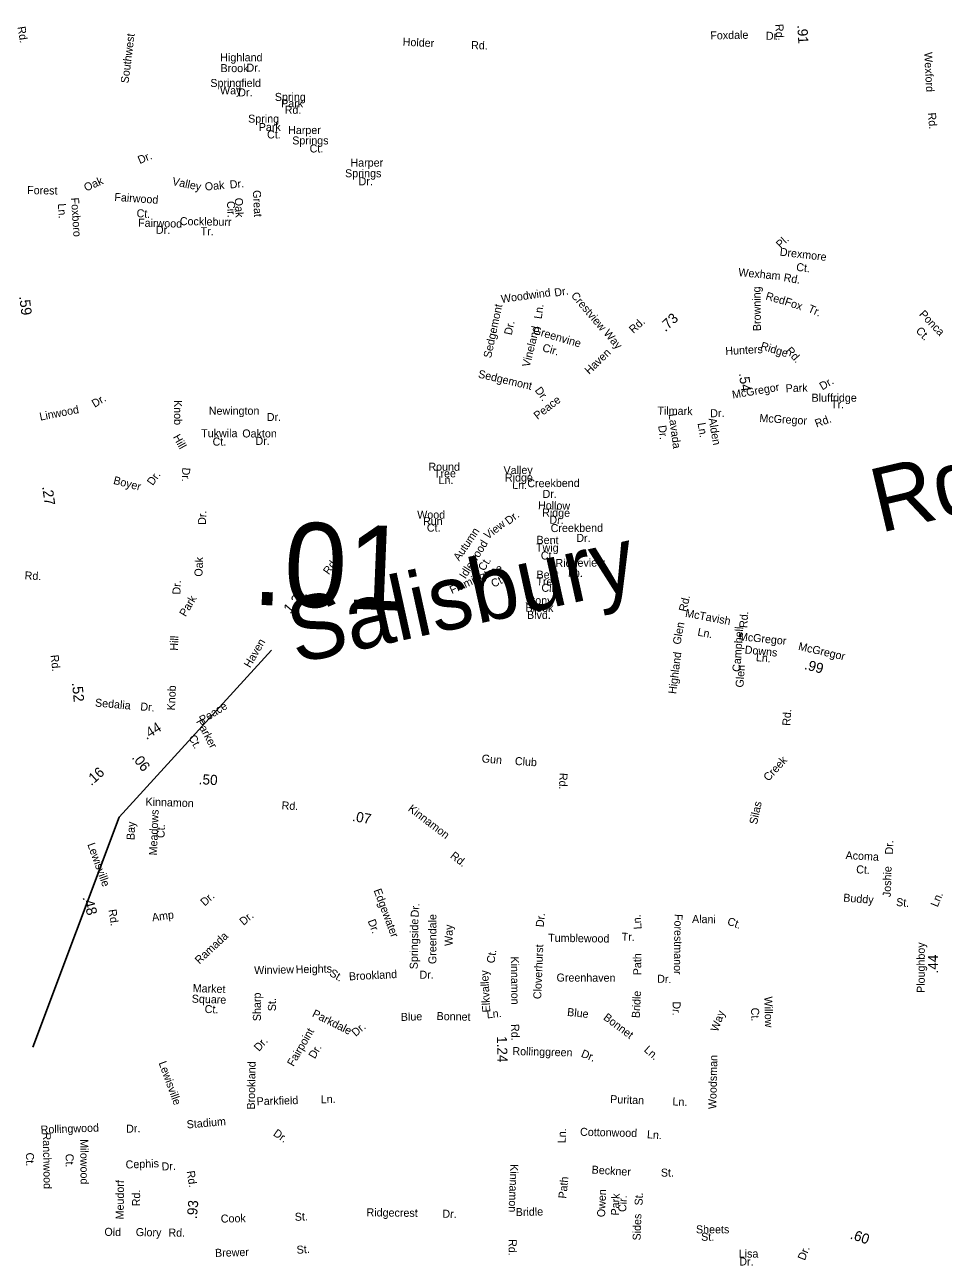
# Model space of a CAD drawing. Extents: x 1553981 to 1780076, y 812965 to 996873.
# Drawn here: x 1628136 to 1629499, y 845055 to 846888 of the extents above; entities that cross this region are included whole.
import ezdxf

# ---------------------------------------------------------------- set-up
doc = ezdxf.new("R2010")
doc.units = 0
for name, color, linetype in [('Exist Road Non-System Type 51 Label', 7, 'Continuous'), ('Exist Road Primary NC Service Mileage Hundredths English Label', 7, 'Continuous'), ('Exist Road Secondary Mileage Hundredths English Label', 7, 'Continuous'), ('Map Preparation Border Antique Large Shape', 7, 'Continuous')]:
    doc.layers.add(name, color=color, linetype=linetype)

msp = doc.modelspace()

# ---------------------------------------------------------------- linework, layer by layer
at = {"layer": 'Exist Road Primary NC Service Mileage Hundredths English Label'}
msp.add_lwpolyline([(1628148.4, 845370.8), (1628276.4, 845712.3), (1628502.7, 845959.8)], dxfattribs=at)

# ---------------------------------------------------------------- texts
at = {"layer": 'Exist Road Non-System Type 51 Label'}
for s, height, rotation, p in [('Southwest', 11.88, 82.8093, (1628290.4, 846800.4)), ('Foxdale', 11.88, 1.1551, (1629153.9, 846865.9)), ('Dr.', 11.88, 0.1484, (1629236.3, 846865.4)), ('Wexford', 11.88, 272.8828, (1629471.1, 846846.8)), ('Rd.', 11.88, 274.1819, (1629476.7, 846757.1)), ('Dr.', 11.88, 22.5389, (1628307.1, 846681)), ('Oak', 11.88, 24.0138, (1628227.5, 846640.2)), ('Valley', 11.88, 348.2903, (1628354.6, 846650.2)), ('Oak', 11.88, 5.1478, (1628404.2, 846641.7)), ('Dr.', 11.88, 5.1478, (1628441.1, 846644.8)), ('Forest', 11.87, 359.1622, (1628140, 846636.5)), ('Fairwood', 11.87, 356.1521, (1628269.2, 846626.5)), ('Great', 11.88, 272.9588, (1628474.9, 846642.1)), ('Ln.', 11.88, 273.727, (1628185.6, 846622.3)), ('Foxboro', 11.88, 273.727, (1628205.1, 846631)), ('Ct.', 11.87, 356.1521, (1628302.1, 846602.5)), ('Cir.', 11.88, 272.9588, (1628436.4, 846626)), ('Oak', 11.88, 272.9588, (1628448.1, 846630.8)), ('Fairwood', 11.88, 358.6849, (1628304.6, 846588.2)), ('Cockleburr', 11.88, 359.1641, (1628366.5, 846590.5)), ('Dr.', 11.88, 359.8348, (1628331.1, 846577.6)), ('Tr.', 11.88, 359.8911, (1628397.5, 846575.5)), ('Pl.', 11.88, 44.5487, (1629258.2, 846555.3)), ('Drexmore', 11.87, 353.4121, (1629256.4, 846545.3)), ('Wexham', 11.88, 354.6164, (1629195, 846515)), ('Ct.', 11.87, 353.4121, (1629280.8, 846522.8)), ('Rd.', 11.88, 350.3022, (1629261.9, 846507.5)), ('Woodwind', 11.88, 7.6702, (1628843.9, 846475.1)), ('Dr.', 11.87, 8.7183, (1628923.1, 846484.4)), ('Crestview', 11.87, 310.2266, (1628946.4, 846485.5)), ('Browning', 11.87, 90.737, (1629229, 846433.4)), ('Red', 11.87, 344.0848, (1629235, 846480.3)), ('Sedgemont', 11.87, 78.0484, (1628828.5, 846392.6)), ('Ln.', 11.88, 82.0714, (1628903.5, 846450.7)), ('Fox', 11.88, 341.2075, (1629263.1, 846472.4)), ('Tr.', 11.88, 335.8899, (1629297.6, 846462.3)), ('Ponca', 11.88, 313.9481, (1629462.9, 846457.6)), ('Dr.', 11.87, 78.0484, (1628859.1, 846426.7)), ('Vineland', 11.88, 75.908, (1628885.6, 846379)), ('Greenvine', 11.88, 343.5821, (1628889.6, 846429.6)), ('Way', 11.88, 310.3872, (1628994.6, 846429.6)), ('Ct.', 11.88, 313.9481, (1629457.9, 846432.9)), ('Cir.', 11.88, 343.5821, (1628903.6, 846403.8)), ('Ridge', 11.88, 343.0177, (1629227.4, 846406.4)), ('Hunters', 11.87, 3.0483, (1629176.4, 846397.8)), ('Rd.', 11.88, 311.7419, (1629264.9, 846403.6)), ('Sedgemont', 11.88, 346.7936, (1628808.5, 846364.5)), ('Dr.', 11.88, 30.6105, (1629320, 846345.2)), ('Dr.', 11.88, 306.0677, (1628892.8, 846345.3)), ('McGregor', 11.88, 9.6913, (1629187.1, 846333)), ('Park', 11.87, 1.7234, (1629265.7, 846342.5)), ('Bluffridge', 11.88, 0.0308, (1629304, 846328.5)), ('Linwood', 11.87, 11.1114, (1628159.6, 846300.4)), ('Dr.', 11.87, 31.3819, (1628240.3, 846319.4)), ('Knob', 11.88, 270.0359, (1628358, 846331)), ('Tilmark', 11.88, 358.9481, (1629075.2, 846309.5)), ('Tr.', 11.88, 359.6474, (1629332.9, 846318.7)), ('Lavada', 11.88, 277.4273, (1629091.9, 846310)), ('Alden', 11.87, 279.7001, (1629151.1, 846303.4)), ('Dr.', 11.88, 1.2008, (1629153.7, 846305.4)), ('McGregor', 11.88, 356.6429, (1629226.4, 846298.6)), ('Rd.', 11.88, 19.6806, (1629311.4, 846290.1)), ('Dr.', 11.88, 277.4273, (1629076.4, 846292.8)), ('Ln.', 11.87, 279.7001, (1629134.8, 846296.5)), ('Hill', 11.88, 299.3856, (1628356, 846276.2)), ('Rd.', 95, 13.2541, (1629405.5, 846133.7)), ('Dr.', 11.88, 268.3918, (1628370.2, 846230.9)), ('Round', 11.88, 359.8147, (1628735.4, 846226.2)), ('Valley', 11.88, 0.5508, (1628847, 846221)), ('Boyer', 11.88, 345.6166, (1628267.1, 846206.8)), ('Dr.', 11.88, 54.4408, (1628326.4, 846203.3)), ('Tree', 11.88, 1.5489, (1628743.8, 846215.6)), ('Ln.', 11.88, 1.0362, (1628750.6, 846206.2)), ('Ridge', 11.88, 0.0408, (1628849, 846210.1)), ('Ln.', 11.88, 358.3761, (1628859.7, 846199.4)), ('Creekbend', 11.88, 0.3489, (1628882.2, 846201.6)), ('Dr.', 11.88, 359.1805, (1628904.8, 846185.9)), ('Hollow', 11.88, 359.1312, (1628898, 846168.9)), ('Dr.', 11.87, 87.6316, (1628405.2, 846145.6)), ('Wood', 11.87, 0.2182, (1628718.9, 846154.9)), ('Run', 11.87, 0.2182, (1628727.5, 846145.3)), ('Dr.', 11.88, 37.9572, (1628854.8, 846145.4)), ('Ridge', 11.88, 359.1312, (1628904.1, 846158.2)), ('Dr.', 11.88, 359.1312, (1628914.9, 846147.5)), ('Ct.', 11.87, 0.2182, (1628733.2, 846135.7)), ('Autumn', 11.88, 55.6702, (1628781.1, 846091.4)), ('View', 11.88, 37.9572, (1628823.6, 846123.6)), ('Creekbend', 11.88, 0.3489, (1628916.9, 846135.1)), ('Salisbury', 95, 12.3963, (1628538.8, 845939.6)), ('Idlewood', 11.87, 57.7093, (1628790.3, 846064.8)), ('Twig', 11.87, 359.3642, (1628895.1, 846106.3)), ('Bent', 11.88, 358.7938, (1628895.8, 846117.8)), ('Dr.', 11.88, 359.1805, (1628954.9, 846120.6)), ('Ct.', 11.88, 359.3905, (1628902.2, 846094.5)), ('Oak', 11.87, 87.6316, (1628400, 846068.8)), ('Flamingtree', 11.875, 24.5805, (1628770.3, 846042.9)), ('Ct.', 11.87, 57.7093, (1628818.2, 846076.4)), ('Ridgeview', 11.88, 0.7213, (1628924.1, 846083.2)), ('Ct.', 11.87, 26.6857, (1628832, 846052.4)), ('Tree', 11.88, 359.7112, (1628895.7, 846056)), ('Bent', 11.88, 359.8074, (1628895.9, 846066.1)), ('Ln.', 11.88, 359.0579, (1628942.5, 846068.8)), ('Dr.', 11.88, 87.4647, (1628367.4, 846042.2)), ('Cir.', 11.88, 358.2043, (1628903, 846046.7)), ('Park', 11.88, 59.1418, (1628375.2, 846008.6)), ('Stony', 11.87, 359.7052, (1628879, 846028)), ('Brook', 11.88, 359.691, (1628879.4, 846016.9)), ('Rd.', 11.88, 76.9514, (1629118.3, 846016.2)), ('Blvd.', 11.88, 359.9067, (1628881.8, 846006.3)), ('McTavish', 11.88, 349.3867, (1629115.9, 846009.6)), ('Rd.', 11.87, 86.2284, (1629208.5, 845992.5)), ('Glen', 11.88, 79.9122, (1629109.5, 845967.5)), ('Ln.', 11.88, 349.3867, (1629134.1, 845981.6)), ('Campbell', 11.88, 86.2283, (1629198.3, 845927.4)), ('Hill', 11.88, 87.5266, (1628363.6, 845959)), ('McGregor', 11.87, 354.2881, (1629195.8, 845974.7)), ('Highland', 11.87, 82.7734, (1629103, 845894.4)), ('Downs', 11.87, 354.2881, (1629204.4, 845955.1)), ('Ln.', 11.87, 354.2881, (1629221, 845943.8)), ('Glen', 11.88, 86.2283, (1629202.9, 845904.2)), ('Knob', 11.88, 87.5266, (1628359.3, 845870.4)), ('Sedalia', 11.88, 355.0483, (1628240.4, 845876.4)), ('Dr.', 11.88, 355.0483, (1628307.6, 845870.6)), ('Rd.', 11.88, 86.5452, (1629272.4, 845847.4)), ('Parker', 11.88, 297.9277, (1628390.4, 845854.2)), ('Ct.', 11.88, 297.9277, (1628379.3, 845830.5)), ('Gun', 11.88, 355.2131, (1628814.2, 845793.5)), ('Club', 11.87, 356.3625, (1628863.5, 845789.7)), ('Creek', 11.88, 47.3473, (1629240, 845764.6)), ('Rd.', 11.87, 268.0005, (1628930.1, 845778)), ('Silas', 11.88, 77.862, (1629223, 845700.6)), ('Meadows', 11.88, 87.7816, (1628332.6, 845655.3)), ('Bay', 11.88, 87.7816, (1628299.3, 845678)), ('Ct.', 11.88, 87.7816, (1628343.8, 845681)), ('Acoma', 11.88, 356.9247, (1629354.2, 845650)), ('Dr.', 11.87, 88.4653, (1629424.9, 845656.6)), ('Ct.', 11.88, 356.9247, (1629370, 845629)), ('Joshie', 11.88, 88.3504, (1629421.5, 845593.4)), ('Edgewater', 11.88, 290.6162, (1628654, 845603.6)), ('Dr.', 11.88, 42.0016, (1628403.6, 845579.5)), ('Buddy', 11.87, 355.7632, (1629350.8, 845587)), ('St.', 11.88, 355.0859, (1629429.1, 845580.5)), ('Amp', 11.88, 7.9052, (1628326, 845557.5)), ('Dr.', 11.87, 39.8239, (1628461.1, 845550.8)), ('Dr.', 11.88, 85.8091, (1628720.8, 845563.1)), ('Dr.', 11.88, 84.1789, (1628906.4, 845548.5)), ('Dr.', 11.88, 290.6162, (1628645.2, 845558.2)), ('Springside', 11.87, 89.2853, (1628719.6, 845486.5)), ('Greendale', 11.88, 89.9698, (1628747.3, 845494.2)), ('Way', 11.88, 89.9698, (1628771.5, 845521.1)), ('Ln.', 11.88, 94.1349, (1629051.9, 845546.2)), ('Forestmanor', 11.875, 269.3092, (1629100.7, 845568.6)), ('Alani', 11.87, 359.2606, (1629126.6, 845555.2)), ('Ct.', 11.88, 339.7117, (1629177.9, 845553.2)), ('Ramada', 11.88, 43.2032, (1628395.6, 845493.4)), ('Tumblewood', 11.87, 359.2204, (1628913.1, 845527.3)), ('Tr.', 11.88, 358.1882, (1629022.1, 845528.9)), ('Ct.', 11.88, 81.0446, (1628833.3, 845494.7)), ('Cloverhurst', 11.875, 87.7669, (1628902.8, 845442)), ('Path', 11.88, 89.9703, (1629051.2, 845477.6)), ('Winview', 11.88, 1.2013, (1628477, 845479.2)), ('Heights', 11.88, 1.2013, (1628538.6, 845480.5)), ('St.', 11.88, 329.2852, (1628587.6, 845477.7)), ('Brookland', 11.87, 2.8649, (1628617.8, 845470)), ('Dr.', 11.88, 0.6836, (1628722.3, 845472.4)), ('Elkvalley', 11.88, 93.0592, (1628827.4, 845422.8)), ('Greenhaven', 11.88, 359.7864, (1628925.6, 845468.3)), ('Dr.', 11.88, 357.9708, (1629074.7, 845466.6)), ('Market', 11.87, 358.1733, (1628385.6, 845452.7)), ('Square', 11.87, 358.1733, (1628384.2, 845437)), ('Sharp', 11.88, 89.9504, (1628486.9, 845409.5)), ('St.', 11.88, 89.9504, (1628509.2, 845424.3)), ('Bridle', 11.88, 87.1975, (1629049, 845413.9)), ('Willow', 11.88, 271.4111, (1629233.9, 845446)), ('Ct.', 11.87, 358.1733, (1628403.3, 845421.7)), ('Parkdale', 11.88, 333.3203, (1628561.9, 845417)), ('Blue', 11.88, 1.9762, (1628694.7, 845409.8)), ('Bonnet', 11.88, 358.5156, (1628747.5, 845411.3)), ('Ln.', 11.87, 5.5117, (1628822.5, 845413.6)), ('Blue', 11.88, 354.28, (1628940.9, 845417.4)), ('Dr.', 11.87, 269.6475, (1629097.9, 845438.9)), ('Way', 11.88, 69.9434, (1629164.8, 845392.9)), ('Ct.', 11.88, 271.4111, (1629214.2, 845429.4)), ('Dr.', 11.88, 40.2986, (1628627.5, 845386)), ('Bonnet', 11.87, 322.8937, (1628994, 845412.9)), ('Fairpoint', 11.88, 59.7191, (1628535.2, 845341.4)), ('Dr.', 11.88, 48.5124, (1628484.1, 845363.8)), ('Dr.', 11.88, 59.7191, (1628566.9, 845352.8)), ('Rollinggreen', 11.875, 358.5885, (1628860, 845359.3)), ('Dr.', 11.88, 337.5156, (1628961, 845357.1)), ('Ln.', 11.88, 318.42, (1629054.4, 845365.6)), ('Brookland', 11.87, 89.064, (1628477.9, 845278.3)), ('Woodsman', 11.88, 88.6514, (1629162.5, 845278.9)), ('Parkfield', 11.88, 1.6896, (1628480.7, 845284.7)), ('Ln.', 11.88, 1.6896, (1628575.9, 845287.6)), ('Puritan', 11.87, 357.8499, (1629005, 845288)), ('Ln.', 11.87, 357.4486, (1629097.4, 845284.6)), ('Rollingwood', 11.875, 2.0815, (1628160.3, 845242.6)), ('Stadium', 11.88, 4.8811, (1628377.3, 845250.3)), ('Ranchwood', 11.87, 270.9712, (1628163.2, 845244.2)), ('Dr.', 11.88, 2.0815, (1628287.1, 845243.9)), ('Dr.', 11.88, 324.8943, (1628504.2, 845240.7)), ('Ln.', 11.88, 87.6938, (1628939, 845228.2)), ('Cottonwood', 11.87, 358.6509, (1628960.4, 845239.5)), ('Ln.', 11.88, 356.0498, (1629059.5, 845235.9)), ('Milowood', 11.88, 270.6056, (1628218.7, 845234.4)), ('Ct.', 11.87, 270.9712, (1628138.2, 845214.5)), ('Ct.', 11.88, 270.6056, (1628197.1, 845212.8)), ('Cephis', 11.88, 2.2975, (1628286.4, 845190.8)), ('Dr.', 11.88, 2.2975, (1628339.8, 845187.9)), ('Beckner', 11.88, 356.4412, (1628977.4, 845183.5)), ('Meudorf', 11.87, 89.6138, (1628283.3, 845115.4)), ('Path', 11.87, 84.3676, (1628940, 845145.9)), ('Rd.', 11.87, 89.6138, (1628307.6, 845134.8)), ('Owen', 11.87, 87.5348, (1628997.5, 845118.5)), ('Park', 11.87, 87.5348, (1629018, 845121)), ('Cir.', 11.87, 87.5348, (1629028.9, 845126.2)), ('St.', 11.88, 87.219, (1629053.1, 845135.8)), ('Ridgecrest', 11.88, 359.2672, (1628643.6, 845120)), ('Dr.', 11.88, 359.2319, (1628756.1, 845117.9)), ('Bridle', 11.88, 1.3277, (1628865.2, 845120.3)), ('Cook', 11.88, 1.1166, (1628427.5, 845110.6)), ('St.', 11.87, 2.2342, (1628537.4, 845113.2)), ('Sides', 11.88, 88.1489, (1629050.3, 845084)), ('Old', 11.88, 358.807, (1628254.6, 845091.1)), ('Glory', 11.88, 359.1742, (1628301.2, 845090.7)), ('Rd.', 11.88, 359.1742, (1628349.7, 845090)), ('St.', 11.87, 3.9172, (1628540.3, 845064.3)), ('Brewer', 11.87, 1.5495, (1628419, 845059.8)), ('Dr.', 11.88, 68.2206, (1629293.9, 845053.6))]:
    msp.add_text(s, height=height, rotation=rotation, dxfattribs=at).set_placement(p)
for s, height, p in [('Highland', 11.88, (1628426.6, 846833.5)), ('Brook', 11.88, (1628427, 846817.5)), ('Dr.', 11.88, (1628465.5, 846818.2)), ('Springfield', 11.875, (1628411.9, 846795.5)), ('Way', 11.88, (1628426.2, 846784.5)), ('Dr.', 11.88, (1628453.3, 846781.5)), ('Spring', 11.88, (1628507.6, 846774.8)), ('Park', 11.88, (1628516.9, 846765.3)), ('Rd.', 11.88, (1628522.2, 846755.7)), ('Spring', 11.88, (1628468, 846742.5)), ('Park', 11.88, (1628483.7, 846730.1)), ('Ct.', 11.88, (1628496, 846719.1)), ('Harper', 11.88, (1628527.3, 846725.6)), ('Springs', 11.88, (1628533.4, 846710.2)), ('Ct.', 11.88, (1628559.2, 846698.3)), ('Harper', 11.88, (1628619.8, 846677.3)), ('Springs', 11.88, (1628611.8, 846661.5)), ('Dr.', 11.88, (1628631.9, 846649.6)), ('Newington', 11.88, (1628409.6, 846309.2)), ('Dr.', 11.88, (1628495.6, 846299.9)), ('Tukwila', 11.88, (1628398.3, 846275.9)), ('Oakton', 11.88, (1628459.3, 846275.5)), ('Ct.', 11.88, (1628415.2, 846263.4)), ('Dr.', 11.88, (1628478.9, 846264.5)), ('St.', 11.88, (1629080.4, 845178.9)), ('Sheets', 11.88, (1629132.5, 845094.7)), ('St.', 11.88, (1629140.2, 845083.7)), ('Lisa', 11.88, (1629195.9, 845058.7)), ('Dr.', 11.88, (1629196.8, 845047))]:
    msp.add_text(s, height=height, dxfattribs=at).set_placement(p)
at = {"layer": 'Exist Road Primary NC Service Mileage Hundredths English Label'}
msp.add_text('.01', height=125, rotation=357.6338, dxfattribs=at).set_placement((1628472.7, 846027.6))
at = {"layer": 'Exist Road Secondary Mileage Hundredths English Label'}
for s, height, rotation, p in [('.91', 15, 273.1869, (1629282.9, 846887)), ('.59', 15.62, 277.4119, (1628128.1, 846484.7)), ('.73', 15, 43.2263, (1629087.2, 846431.5)), ('.54', 15, 276.7626, (1629196.3, 846370.5)), ('.27', 15.62, 278.026, (1628162.3, 846202.4)), ('1.22', 15, 49.416, (1628530.4, 846013.1)), ('.99', 15, 345.3905, (1629292.4, 845932)), ('.52', 15.62, 275.6154, (1628206.5, 845911.4)), ('.44', 15, 32.2817, (1628317.2, 845826.6)), ('.06', 15, 308.2474, (1628294.7, 845800.3)), ('.16', 15, 41.6996, (1628235.2, 845758.1)), ('.50', 15, 356.7264, (1628394.4, 845761.2)), ('.07', 15, 349.8688, (1628621.7, 845706.7)), ('.48', 15.62, 284.9684, (1628222, 845593.2)), ('.44', 15, 89.9564, (1629491.8, 845480.2)), ('1.24', 15, 271.3223, (1628837.1, 845387.2)), ('.93', 15, 85.1051, (1628391.8, 845115.5)), ('.60', 15, 341.0692, (1629360.3, 845087.2))]:
    msp.add_text(s, height=height, rotation=rotation, dxfattribs=at).set_placement(p)
at = {"layer": 'Map Preparation Border Antique Large Shape'}
for s, height, rotation, p in [('Rd.', 11.87, 279.1676, (1628125.7, 846884.4)), ('Rd.', 11.88, 271.5122, (1629250.4, 846888.8)), ('Holder', 11.87, 357.3232, (1628697.1, 846856.7)), ('Rd.', 11.88, 358.115, (1628798.6, 846851.8)), ('Rd.', 11.88, 43.2062, (1629039.8, 846429.1)), ('Haven', 11.87, 44.1415, (1628974.2, 846368.2)), ('Peace', 11.88, 38.0695, (1628897.4, 846301.4)), ('Rd.', 11.88, 54.0548, (1628587.7, 846070.9)), ('Rd.', 11.88, 356.9385, (1628136.1, 846065)), ('Haven', 11.88, 59.7387, (1628470.9, 845932.8)), ('McGregor', 11.88, 347.0424, (1629283.5, 845960.5)), ('Rd.', 11.88, 275.6534, (1628174.9, 845952.5)), ('Peace', 11.88, 32.216, (1628400.2, 845850.1)), ('Kinnamon', 11.88, 358.1198, (1628315.5, 845729.3)), ('Rd.', 11.88, 357.1379, (1628517.4, 845723.8)), ('Kinnamon', 11.88, 322.679, (1628704.2, 845722.5)), ('Lewisville', 11.88, 289.9215, (1628229.2, 845671.7)), ('Rd.', 11.88, 322.1086, (1628766.9, 845652.8)), ('Ln.', 11.87, 67.4003, (1629491, 845577.9)), ('Rd.', 11.88, 278.4952, (1628260.7, 845574.7)), ('Ploughboy', 11.87, 89.9564, (1629472, 845451.4)), ('Kinnamon', 11.87, 270.7326, (1628857.7, 845505.5)), ('Rd.', 11.88, 271.3153, (1628858.2, 845405.2)), ('Lewisville', 11.88, 289.9215, (1628335, 845347.7)), ('Rd.', 11.88, 278.4952, (1628376.8, 845186.8)), ('Kinnamon', 11.87, 267.8025, (1628857.1, 845197.6)), ('Rd.', 11.88, 269.2378, (1628854.7, 845086.2))]:
    msp.add_text(s, height=height, rotation=rotation, dxfattribs=at).set_placement(p)

doc.saveas('drawing.dxf')
